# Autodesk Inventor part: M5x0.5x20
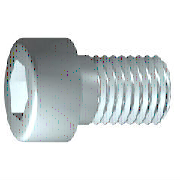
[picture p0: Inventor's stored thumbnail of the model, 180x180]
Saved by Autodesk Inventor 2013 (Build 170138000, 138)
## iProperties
IsCustomPart: 0
Company: 한국ATC센터
Created: 2014-07
Part Number: M5x0.5x20
Material: Steel, Mild
Description: 6각머리 태핑 나사
Document SubType Name: Modeling
Standard: KS B 1003
Designer: KYOUNG IL JANG
Standards Organization: KS
Language: ko-KR
Size Designation: M 5 x 20
Categories: <MemberInstance><Categories><Category DisplayName="조임쇠" InternalName="e4da775c-781d-43d5-af7c-5136215cf5a6" Mnemonic="FSTN"><Category DisplayName="볼트" InternalN
Density: 7.86 g/cm^3
Mass: 4.9629 g
Surface Area: 5.88237 cm^2
Volume: 0.631412 cm^3
Author: KYOUNG IL JANG
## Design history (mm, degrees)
revolve "본체" stored, may be unused: angle "d10" = 90 deg
sketch "스케치2"
  geometry: L1 (0, -5.95)-(0, 5.95) reference; L2 (-5.95, 0)-(5.95, 0) reference; L3 (2.309, 0)-(1.155, -2); L4 (1.155, -2)-(-1.155, -2); L5 (-1.155, -2)-(-2.309, 0); L6 (-2.309, 0)-(-1.155, 2); L7 (-1.155, 2)-(1.155, 2); L8 (1.155, 2)-(2.309, 0); 2 further points
  constraints: 12 end point, 1 coincident, 1 horizontal alignment, 1 point on line, 12 other
extrude "슬롯" join sketch "스케치2" stored distance "d11" = 10; taper "d12" = 0 deg
workplane "Work Plane1"
fillet "Fillet2" dims "d30" = 0.1 (= R)
body "Solid1"
fillet "모깎기1" dims "d17" = 0.5 (= RR)
feature "스레드" dims "d13" = 18 (= GEL), "d14" = 0
chamfer "모따기1" distance "d15" = 0.49076 (= -0.5 x SPD + 0.5 x GD); stored, may be unused: second distance "d16" = 0.49076 (= GUL), angle "d27" = 45 deg
sketch "스케치1"
  geometry: L1 (-1.167, 0)-(20, 0); L2 (20, 0)-(20, 2.5); L3 (20, 2.5)-(2, 2.5); L4 (2, 2.5)-(1.509, 2.5); L5 (1.509, 2.5)-(0, 2.5); L6 (0, 2.5)-(0, 4.25); L7 (0, 4.25)-(-5, 4.25); L8 (-5, 4.25)-(-5, 2.309); L9 (-5, 2.309)-(-2.5, 2.309); L10 (-2.5, 2.309)-(-1.167, 0); L11 (-10, 0)-(25, 0) reference; L12 (0, -0.85)-(0, 5.1) reference; L13 (2, 2.5)-(0, 2.5)
  constraints: 22 end point, 6 parallel, 2 collinear, 2 perpendicular, 1 horizontal, 1 point on line
  dimensions: "d1" = 18 distance from line of L3.end L2 (= GEL); "d2" = 0.49086 distance of L4.end L3.end (computed from GAL); "d3" = 5 distance between parallel lines of L8 L6 (= KOH); "d4" = 2.5 distance of L8.end L9.end (= INTI); "d5" = 60 deg angle of L10 L1; "d6" = 5 diameter of L3 L1 (= GD); "d7" = 5 diameter of L5 L1 (= BDM); "d8" = 4.6188 diameter of L9 L1 (= 1.1547 x SW); "d9" = 8.5 diameter of L7 L1 (= KOD); "d26" = 20 distance between parallel lines of L12 L2 (= NLG)
other parameters: "GD" = 5 (= NND) [user parameter; used in 2 equation terms], "NLG" = 20 [user parameter; used in 1 equation term], "GEL" = 18 [user parameter; used in 2 equation terms], "KOD" = 8.5 [user parameter; used in 1 equation term], "KOH" = 5 [user parameter; used in 1 equation term], "INTI" = 2.5 [user parameter; used in 1 equation term], "GAL" = 0.49076 (= 0.61345 x PTC) [user parameter; used in 1 equation term], "GUL" = 0.49076 (= 0.61345 x PTC) [user parameter; used in 1 equation term], "BDM" = 5 (= NND) [user parameter; used in 1 equation term], "SW" = 4 [user parameter; used in 2 equation terms], "RR" = 0.5 [user parameter; used in 1 equation term], "SPD" = 4.01848 (= NND - 1.2269 x PTC) [user parameter; used in 1 equation term], "d19" = 0, "d28" = 0, "d29" = 0, "R" = 0.1 [user parameter; used in 1 equation term], "PHH" = 0.2 [user parameter], "GD1" = 4.01848 (= THREADDIA - 1.2269 x PTC) [user parameter], "THREADDIA" = 5 [user parameter; used in 1 equation term], "FAWI" = 45 deg [user parameter], "TPU" = 12.5 (computed from PTC) [user parameter], "PTC" = 0.8 [user parameter; used in 5 equation terms], "NND" = 5 [user parameter; used in 3 equation terms], "TOA" = 30 deg [user parameter], "E0" = 4.62 (= 1.155 x SW) [user parameter]
